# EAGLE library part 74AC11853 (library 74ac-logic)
PARITY GENERATOR/CHECKER
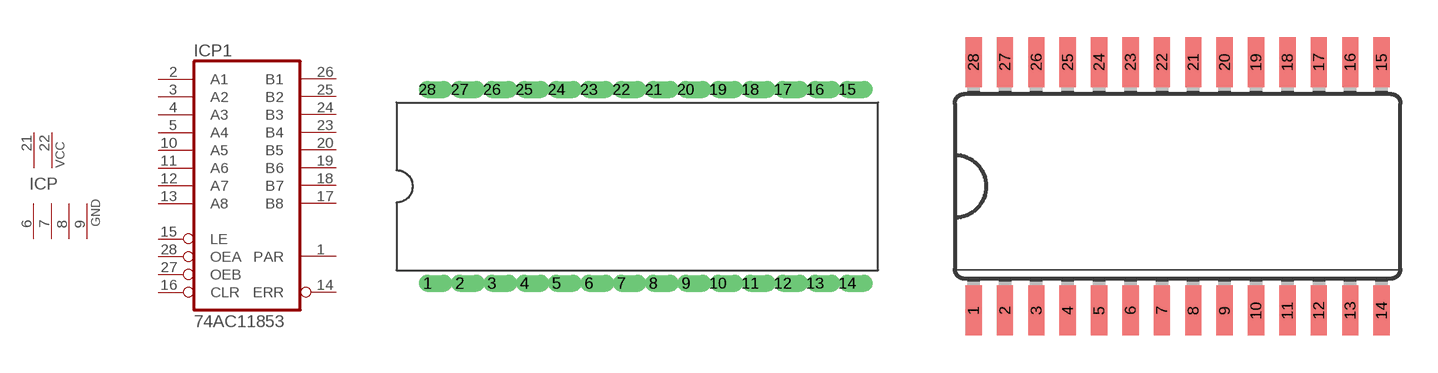
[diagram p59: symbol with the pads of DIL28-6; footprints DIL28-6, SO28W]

Designator prefix IC; gates P1=7411853 P=2PWR4GND

## 74AC11853  [DIL28-6]
1  P1:PAR
2  P1:A1
3  P1:A2
4  P1:A3
5  P1:A4
6  P:GND  pwr
7  P:GND  pwr
8  P:GND  pwr
9  P:GND  pwr
10  P1:A5
11  P1:A6
12  P1:A7
13  P1:A8
14  P1:ERR
15  P1:LE  in
16  P1:CLR  in
17  P1:B8
18  P1:B7
19  P1:B6
20  P1:B5
21  P:VCC  pwr
22  P:VCC  pwr
23  P1:B4
24  P1:B3
25  P1:B2
26  P1:B1
27  P1:OEB  in
28  P1:OEA  in

## 74AC11853D  [SO28W]
Pads as for DIL28-6

## Footprint DIL28-6 (pad centres in mm)
Dual In Line 0.6 inch
drill 0.813 offset: 1 -16.51,-7.62; 2 -13.97,-7.62; 3 -11.43,-7.62; 4 -8.89,-7.62; 5 -6.35,-7.62; 6 -3.81,-7.62; 7 -1.27,-7.62; 8 1.27,-7.62; 9 3.81,-7.62; 10 6.35,-7.62; 11 8.89,-7.62; 12 11.43,-7.62; 13 13.97,-7.62; 14 16.51,-7.62; 15 16.51,7.62; 16 13.97,7.62; 17 11.43,7.62; 18 8.89,7.62; 19 6.35,7.62; 20 3.81,7.62; 21 1.27,7.62; 22 -1.27,7.62; 23 -3.81,7.62; 24 -6.35,7.62; 25 -8.89,7.62; 26 -11.43,7.62; 27 -13.97,7.62; 28 -16.51,7.62

## Footprint SO28W (pad centres in mm)
Wide Small Outline package 300 mil
smd 0.66 x 2.032: 1 -8.255,-5.029; 2 -6.985,-5.029; 3 -5.715,-5.029; 4 -4.445,-5.029; 5 -3.175,-5.029; 6 -1.905,-5.029; 7 -0.635,-5.029; 8 0.635,-5.029; 9 1.905,-5.029; 10 3.175,-5.029; 11 4.445,-5.029; 12 5.715,-5.029; 13 6.985,-5.029; 14 8.255,-5.029; 15 8.255,5.029; 16 6.985,5.029; 17 5.715,5.029; 18 4.445,5.029; 19 3.175,5.029; 20 1.905,5.029; 21 0.635,5.029; 22 -0.635,5.029; 23 -1.905,5.029; 24 -3.175,5.029; 25 -4.445,5.029; 26 -5.715,5.029; 27 -6.985,5.029; 28 -8.255,5.029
